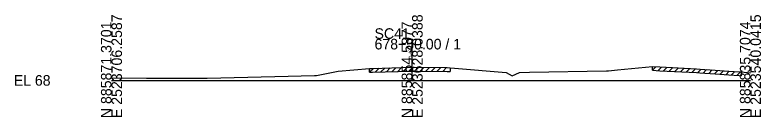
# Model space of a CAD drawing. Extents: x -26 to 183, y -10 to 24021.
# Drawn here: x -25.7 to 172.8, y 10990.3 to 11017.3 of the extents above; entities that cross this region are included whole.
import ezdxf

# ---------------------------------------------------------------- set-up
doc = ezdxf.new("R2010")
doc.units = 0
for name, color, linetype in [('RD_GPK_XS_Cell', 7, 'Continuous'), ('RD_XS_ExGround', 7, 'Continuous'), ('RD_XS_ExPaveRet', 7, 'Continuous'), ('RD_XS_TX_Elev_EX', 7, 'Continuous')]:
    doc.layers.add(name, color=color, linetype=linetype)

msp = doc.modelspace()

# ---------------------------------------------------------------- linework, layer by layer
at = {"layer": 'RD_GPK_XS_Cell'}
for p, q in [((80, 11000), (80, 11011.01)), ((0, 11000), (80, 11000)), ((80, 11000), (170, 11000))]:
    msp.add_line(p, q, dxfattribs=at)
at = {"layer": 'RD_XS_ExGround'}
for p, q in [((60.31, 11002.49), (68.66, 11003.16)), ((68.66, 11003.16), (69.43, 11003.18)), ((69.43, 11003.18), (79.65, 11003.48)), ((79.65, 11003.48), (80, 11003.48)), ((80, 11003.48), (89.31, 11003.38)), ((89.31, 11003.38), (90.12, 11003.37)), ((90.12, 11003.37), (91.25, 11003.27)), ((91.25, 11003.27), (104.98, 11002.1)), ((132.21, 11002.55), (134.62, 11002.8)), ((134.62, 11002.8), (143.92, 11003.67)), ((143.92, 11003.67), (145.88, 11003.57)), ((145.88, 11003.57), (155.69, 11003.06)), ((155.69, 11003.06), (156.53, 11003)), ((156.53, 11003), (160.58, 11002.71)), ((160.58, 11002.71), (164.23, 11002.46)), ((0, 11000.6), (3.04, 11000.71)), ((3.04, 11000.71), (9.3, 11000.57)), ((25.48, 11000.58), (43.46, 11001.02)), ((43.46, 11001.02), (54.02, 11001.31)), ((54.02, 11001.31), (54.59, 11001.33)), ((54.59, 11001.33), (60.31, 11002.49)), ((104.98, 11002.1), (106.61, 11001.22)), ((106.61, 11001.22), (108.59, 11002.07)), ((108.59, 11002.07), (111.18, 11002.14)), ((111.18, 11002.14), (131.69, 11002.56)), ((131.69, 11002.56), (132.21, 11002.55)), ((164.23, 11002.46), (166.98, 11002.27)), ((166.98, 11002.27), (167.5, 11002.24)), ((167.5, 11002.24), (170, 11001.98)), ((9.3, 11000.57), (25.48, 11000.58))]:
    msp.add_line(p, q, dxfattribs=at)
at = {"layer": 'RD_XS_ExPaveRet'}
for p, q in [((68.66, 11002.16), (69.69, 11003.19)), ((68.66, 11002.16), (68.66, 11003.16)), ((70.16, 11002.2), (71.19, 11003.24)), ((71.66, 11002.25), (72.69, 11003.28)), ((73.16, 11002.29), (74.19, 11003.32)), ((74.66, 11002.34), (75.69, 11003.37)), ((76.16, 11002.38), (77.19, 11003.41)), ((77.66, 11002.43), (78.69, 11003.46)), ((79.16, 11002.47), (80.17, 11003.48)), ((80.66, 11002.47), (81.65, 11003.46)), ((82.16, 11002.46), (83.15, 11003.45)), ((83.66, 11002.44), (84.65, 11003.43)), ((85.16, 11002.42), (86.15, 11003.41)), ((86.66, 11002.41), (87.65, 11003.4)), ((88.16, 11002.39), (89.15, 11003.38)), ((90.12, 11003.37), (90.12, 11002.37)), ((143.92, 11002.67), (143.92, 11003.67)), ((143.92, 11002.67), (144.87, 11003.62)), ((145.42, 11002.59), (146.37, 11003.55)), ((146.92, 11002.52), (147.87, 11003.47)), ((148.42, 11002.44), (149.37, 11003.39)), ((149.92, 11002.36), (150.87, 11003.31)), ((151.42, 11002.28), (152.37, 11003.23)), ((152.92, 11002.21), (153.87, 11003.16)), ((154.42, 11002.13), (155.37, 11003.08)), ((155.92, 11002.05), (156.86, 11002.98)), ((157.42, 11001.94), (158.35, 11002.87)), ((158.92, 11001.83), (159.85, 11002.77)), ((68.66, 11002.16), (69.43, 11002.18)), ((69.43, 11002.18), (79.65, 11002.48)), ((79.65, 11002.48), (80, 11002.48)), ((80, 11002.48), (89.31, 11002.38)), ((89.31, 11002.38), (90.12, 11002.37)), ((143.92, 11002.67), (145.88, 11002.57)), ((145.88, 11002.57), (155.69, 11002.06)), ((155.69, 11002.06), (156.53, 11002)), ((156.53, 11002), (160.58, 11001.71)), ((160.42, 11001.73), (161.35, 11002.66)), ((160.58, 11001.71), (164.23, 11001.46)), ((161.92, 11001.62), (162.85, 11002.55)), ((163.42, 11001.51), (164.36, 11002.45)), ((164.23, 11001.46), (166.98, 11001.27)), ((164.92, 11001.41), (165.86, 11002.35)), ((166.42, 11001.31), (167.36, 11002.24)), ((166.98, 11001.27), (167.5, 11001.24)), ((167.5, 11002.24), (167.5, 11001.24))]:
    msp.add_line(p, q, dxfattribs=at)

# ---------------------------------------------------------------- texts
at = {"layer": 'RD_GPK_XS_Cell'}
for s, p in [('E 2523706.2587', (2.8, 10990)), ('E 2523628.0388', (82.8, 10990)), ('E 2523540.0415', (172.8, 10990)), ('N 885871.3701', (0, 10990)), ('N 885854.5877', (80, 10990)), ('N 885835.7074', (170, 10990))]:
    msp.add_text(s, height=2.8, rotation=90, dxfattribs=at).set_placement(p)
for s, p in [('SC41', (70, 11011.01)), ('678+50.00 / 1', (70, 11008.21)), ('EL 68', (-26, 10998.6))]:
    msp.add_text(s, height=2.8, dxfattribs=at).set_placement(p)
at = {"layer": 'RD_XS_TX_Elev_EX'}
msp.add_text('71.48', height=0.8, rotation=90, dxfattribs=at).set_placement((79.9, 11005.48))

doc.saveas('drawing.dxf')
